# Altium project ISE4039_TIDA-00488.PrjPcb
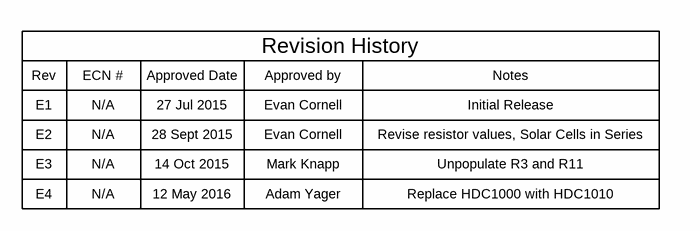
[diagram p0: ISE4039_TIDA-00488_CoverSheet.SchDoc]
TID: TIDA-00488; TechSupport: http://www.ti.com/support; SCH_Rev: E4; PRJ_Title: Energy Harvesting Ambient Light and Environment Sensor Node for Sub-1GHz Networks; PRJ_Number: ISE4039; PRJ_Engineer: Kelly Fernandez; PRJ_Customer: Public Release; PCB_Rev: E4; PCB_Layout: Evan Cornell; EVM_Orderable: N/A; CopyrightYear: 2016
4 sheets, 132 parts. Net scope: global (net labels, ports and power ports of the same name join across sheets).
Board file: ISE4039_TIDA-00488_TID.PcbDoc
Sheets:
  ISE4039_TIDA-00488_CoverSheet.SchDoc
  ISE4039_TIDA-00488_Energy Harvesting.SchDoc
  ISE4039_TIDA-00488_Wireless MCU & Sensors.SchDoc
  ISE4039_TIDA-00488_TID_Hardware.SchDoc

## Sheet ISE4039_TIDA-00488_CoverSheet.SchDoc: Cover Sheet
size 431 x 279 mm; Date: Not shown in title block; ApprovedBy: Not shown in title block; CheckedBy: Not shown in title block; Author: Not shown in title block; CompanyName: Not shown in title block; DrawnBy: Kelly Fernandez; Engineer: Not shown in title block; Organization: Not shown in title block; Address1: Not shown in title block; Address2: Not shown in title block; Address3: Not shown in title block; Address4: Not shown in title block; DocumentNumber: 1; Revision: Use project parameter SCH_Rev; SheetNumber: 1; SheetTotal: 4; PageSetup: Record=PageOptions¦CenterHorizontal=True¦CenterVertical=True¦PrintScale=1.00¦XCorrection=1.00¦YCorrection=1.00¦PrintKind=0¦BorderSize=5000000¦LeftOffset=0¦BottomOffset=0¦Orientation=2¦PaperLength=1000¦PaperWidth=1000¦Scale=100¦PaperSource=15¦PrintQuality=600¦MediaType=1¦DitherType=10¦PaperKind=Letter¦PrintScaleMode=1

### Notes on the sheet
- Rev
- E1
- ECN #
- N/A
- Approved Date
- 27 Jul 2015
- Approved by
- Evan Cornell
- Revision History
- Notes
- Initial Release
- E2
- E3
- 28 Sept 2015
- 14 Oct 2015
- Mark Knapp
- Revise resistor values, Solar Cells in Series
- Unpopulate R3 and R11
- E4
- 12 May 2016
- Adam Yager
- Replace HDC1000 with HDC1010

## Sheet ISE4039_TIDA-00488_Energy Harvesting.SchDoc: Energy Harvesting
size 431 x 279 mm; Date: Not shown in title block; ApprovedBy: Not shown in title block; CheckedBy: Not shown in title block; Author: Not shown in title block; CompanyName: Not shown in title block; DrawnBy: Kelly Fernandez; Engineer: Not shown in title block; Organization: Not shown in title block; Address1: Not shown in title block; Address2: Not shown in title block; Address3: Not shown in title block; Address4: Not shown in title block; DocumentNumber: 2; Revision: Use project parameter SCH_Rev; SheetNumber: 2; SheetTotal: 4; PageSetup: Record=PageOptions¦CenterHorizontal=True¦CenterVertical=True¦PrintScale=0.62¦XCorrection=1.00¦YCorrection=1.00¦PrintKind=0¦BorderSize=5000000¦LeftOffset=0¦BottomOffset=0¦Orientation=2¦PaperLength=1000¦PaperWidth=1000¦Scale=100¦PaperSource=15¦PrintQuality=600¦MediaType=1¦DitherType=10¦PrintScaleMode=1¦PaperKind=Letter
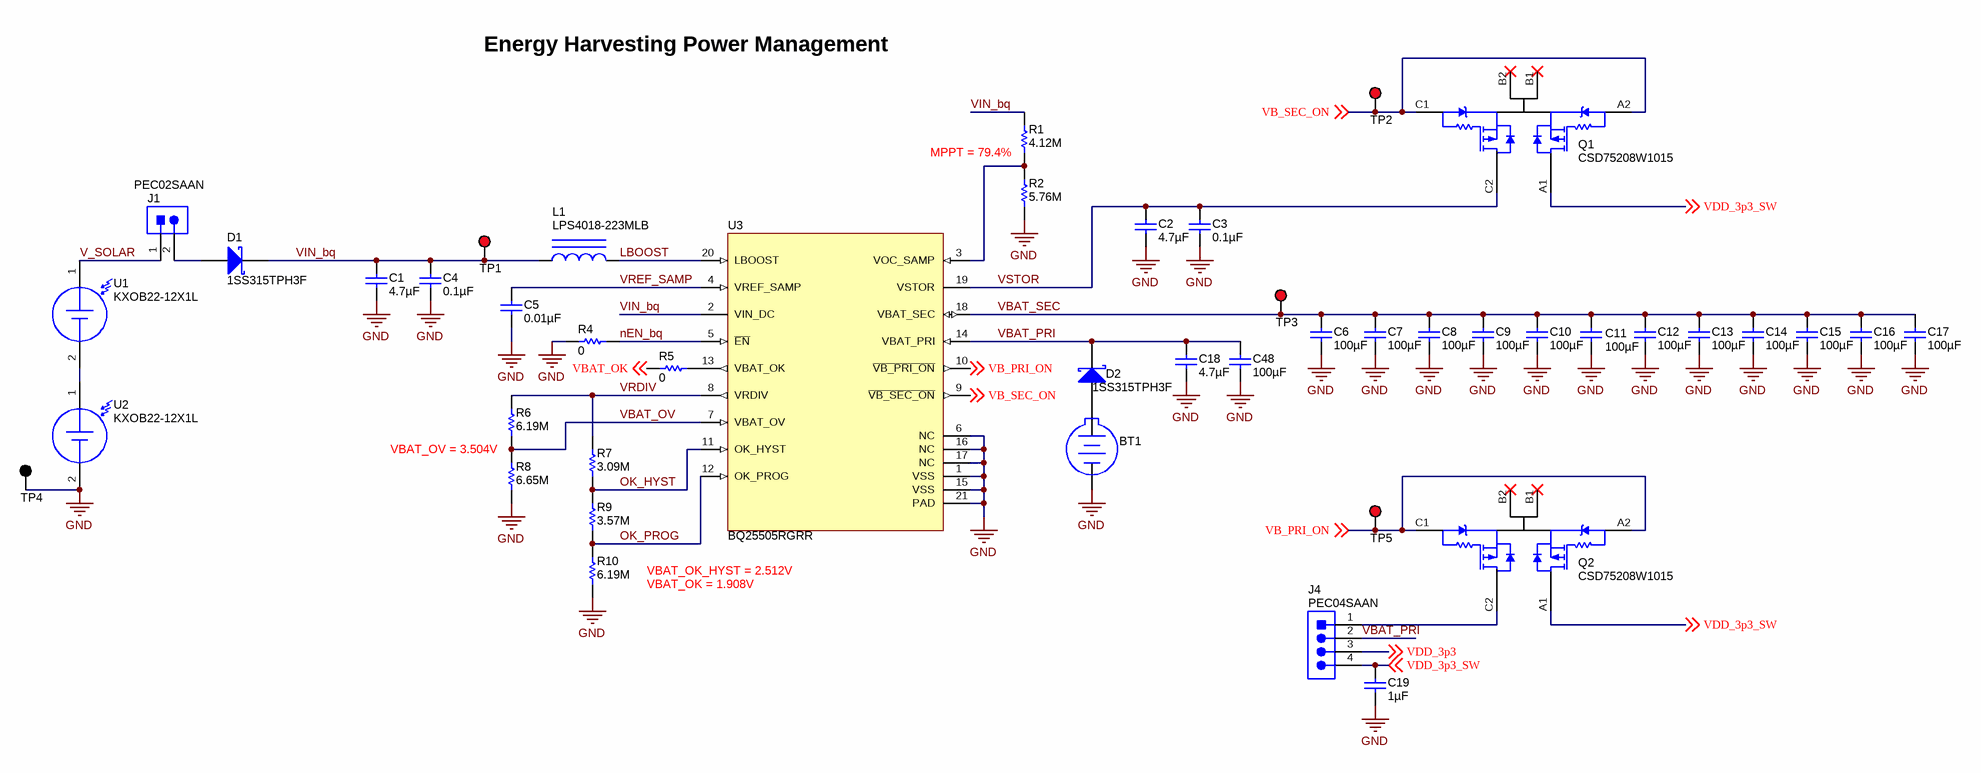
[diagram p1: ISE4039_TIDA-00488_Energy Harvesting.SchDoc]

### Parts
BT1  BS-7  [BAT_BS-7]  (value not drawn)
C1  ValueDisplayed: 4.7µF  [0402]  (hidden comment: C1005X5R1A475K050BC)
C2  ValueDisplayed: 4.7µF  [0402]  (hidden comment: C1005X5R1A475K050BC)
C3  ValueDisplayed: 0.1µF  [0402]  (hidden comment: GRM155R70J104KA01D)
C4  ValueDisplayed: 0.1µF  [0402]  (hidden comment: GRM155R70J104KA01D)
C5  ValueDisplayed: 0.01µF  [0402]  (hidden comment: C0402C103J5RACTU)
C6  ValueDisplayed: 100µF  [1206_190]  (hidden comment: C3216X5R1A107M160AC)
C7  ValueDisplayed: 100µF  [1206_190]  (hidden comment: C3216X5R1A107M160AC)
C8  ValueDisplayed: 100µF  [1206_190]  (hidden comment: C3216X5R1A107M160AC)
C9  ValueDisplayed: 100µF  [1206_190]  (hidden comment: C3216X5R1A107M160AC)
C10  ValueDisplayed: 100µF  [1206_190]  (hidden comment: C3216X5R1A107M160AC)
C11  ValueDisplayed: 100µF  [1206_190]  (hidden comment: C3216X5R1A107M160AC)
C12  ValueDisplayed: 100µF  [1206_190]  (hidden comment: C3216X5R1A107M160AC)
C13  ValueDisplayed: 100µF  [1206_190]  (hidden comment: C3216X5R1A107M160AC)
C14  ValueDisplayed: 100µF  [1206_190]  (hidden comment: C3216X5R1A107M160AC)
C15  ValueDisplayed: 100µF  [1206_190]  (hidden comment: C3216X5R1A107M160AC)
C16  ValueDisplayed: 100µF  [1206_190]  (hidden comment: C3216X5R1A107M160AC)
C17  ValueDisplayed: 100µF  [1206_190]  (hidden comment: C3216X5R1A107M160AC)
C18  ValueDisplayed: 4.7µF  [0402]  (hidden comment: C1005X5R1A475K050BC)
C19  ValueDisplayed: 1µF  [0402]  (hidden comment: GRM155R61A105KE15D)
C48  ValueDisplayed: 100µF  [1206_190]  (hidden comment: C3216X5R1A107M160AC)
D1  1SS315TPH3F  [sod-323]
D2  1SS315TPH3F  [sod-323]
J1  PEC02SAAN  [CONN_PEC02SAAN]
J4  PEC04SAAN  [SULLINS_PEC04SAAN]
L1  LPS4018-223MLB  [LPS4018]
Q1  CSD75208W1015  [YZC0006ABBB]
Q2  CSD75208W1015  [YZC0006ABBB]
R1  ValueDisplayed: 4.12M  [0402]  (hidden comment: CRCW04024M12FKED)
R2  ValueDisplayed: 5.76M  [0402]  (hidden comment: CRCW04025M76FKED)
R4  ValueDisplayed: 0  [0402]  (hidden comment: CRCW04020000Z0ED)
R5  ValueDisplayed: 0  [0402]  (hidden comment: CRCW04020000Z0ED)
R6  ValueDisplayed: 6.19M  [0402]  (hidden comment: CRCW04026M19FKED)
R7  ValueDisplayed: 3.09M  [0402]  (hidden comment: CRCW04023M09FKED)
R8  ValueDisplayed: 6.65M  [0402]  (hidden comment: CRCW04026M65FKED)
R9  ValueDisplayed: 3.57M  [0402]  (hidden comment: CRCW04023M57FKED)
R10  ValueDisplayed: 6.19M  [0402]  (hidden comment: CRCW04026M19FKED)
TP1  5000  [Keystone5000]  (value not drawn)
TP2  5000  [Keystone5000]  (value not drawn)
TP3  5000  [Keystone5000]  (value not drawn)
TP4  5001  [Keystone5001]  (value not drawn)
TP5  5000  [Keystone5000]  (value not drawn)
U1  KXOB22-12X1L  [IXYS_KXOB22-12X1L]
U2  KXOB22-12X1L  [IXYS_KXOB22-12X1L]
U3  BQ25505RGRR  [RGR0020A]

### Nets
GND: BT1.2(-) C1.2 C2.2 C3.2 C4.2 C5.2 C6.2 C7.2 C8.2 C9.2 C10.2 C11.2 C12.2 C13.2 C14.2 C15.2 C16.2 C17.2 C18.2 C19.2 C48.2 R2.1 R4.2 R8.1 R10.1 TP4.1 U2.2(-) U3.1(VSS) U3.6(NC) U3.15(VSS) U3.16(NC) U3.17(NC) U3.21(PAD)
LBOOST: L1.2 U3.20(LBOOST)
nEN_bq: R4.1 U3.5(~{EN})
OK_HYST: R7.1 R9.2 U3.11(OK_HYST)
OK_PROG: R9.1 R10.2 U3.12(OK_PROG)
V_SOLAR: J1.1 U1.1(+)
VB_PRI_ON: Q2.A2(G2) Q2.C1(G1) TP5.1 U3.10(~{VB_PRI_ON}) ; off-sheet VB_PRI_ON
VB_SEC_ON: Q1.A2(G2) Q1.C1(G1) TP2.1 U3.9(~{VB_SEC_ON}) ; off-sheet VB_SEC_ON
VBAT_OK: R5.1 ; off-sheet VBAT_OK
VBAT_OV: R6.1 R8.2 U3.7(VBAT_OV)
VBAT_PRI: C18.1 C48.1 D2.1(K) J4.2 U3.14(VBAT_PRI)
VBAT_SEC: C6.1 C7.1 C8.1 C9.1 C10.1 C11.1 C12.1 C13.1 C14.1 C15.1 C16.1 C17.1 TP3.1 U3.18(VBAT_SEC)
VDD_3p3: J4.3 ; off-sheet VDD_3p3
VDD_3p3_SW: C19.1 J4.4 Q1.A1(D2) Q2.A1(D2) ; off-sheet VDD_3p3_SW
VIN_bq: C1.1 C4.1 D1.1(K) L1.1 R1.2 TP1.1 U3.2(VIN_DC)
VRDIV: R6.2 R7.2 U3.8(VRDIV)
VREF_SAMP: C5.1 U3.4(VREF_SAMP)
VSTOR: C2.1 C3.1 Q1.C2(D1) U3.19(VSTOR)
NetBT1_1: BT1.1(+) D2.2(A)
NetD1_2: D1.2(A) J1.2
NetJ4_1: J4.1 Q2.C2(D1)
NetR1_1: R1.1 R2.2 U3.3(VOC_SAMP)
NetR5_2: R5.2 U3.13(VBAT_OK)
NetU1_2: U1.2(-) U2.1(+)

Not connected (* = marked no-connect by the designer): Q1 B1(S)* B2(S)*; Q2 B1(S)* B2(S)*

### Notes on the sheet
- Energy Harvesting Power Management
- MPPT = 79.4%
- VBAT_OV = 3.504V
- VBAT_OK_HYST = 2.512V
- VBAT_OK = 1.908V

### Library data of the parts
BT1 = BS-7: Battery Holder, CR2032, Retainer clip, TH; Manufacturer: Memory Protection Devices; SymbolCreator: a0412235
C1 C2 C18 = C1005X5R1A475K050BC: CAP, CERM, 4.7 µF, 10 V, +/- 10%, X5R, 0402; Manufacturer: TDK; Polarized: N; CompType: Capacitor; Value: 4.7uF; U/M: EA; Cap_F: 0.0000047; Tolerance_%: 10; Value1: Unknown; Value2: 10V; TaMin_C: -55; TaMax_C: 85; AEC Category: Q200
C3 C4 = GRM155R70J104KA01D: CAP, CERM, 0.1 µF, 6.3 V, +/- 10%, X7R, 0402; Manufacturer: MuRata; Polarized: N; CompType: Capacitor; Value: 0.1uF; U/M: EA; Cap_F: 0.0000001; Tolerance_%: 10; Value1: Unknown; VDC_V: 6.3; Value2: 6.3V; TaMin_C: -55; TaMax_C: 125
C5 = C0402C103J5RACTU: CAP, CERM, 0.01 µF, 50 V, +/- 5%, X7R, 0402; Manufacturer: Kemet; Polarized: N; CompType: Capacitor; Value: 0.01uF; U/M: EA; Cap_F: 0.00000001; Tolerance_%: 5; Value1: Unknown; VDC_V: 50; Value2: 50V; TaMin_C: -55; TaMax_C: 125; AEC Category: Q200
C6-C17 C48 = C3216X5R1A107M160AC: CAP, CERM, 100 µF, 10 V, +/- 20%, X5R, 1206_190; Manufacturer: TDK; Polarized: N; CompType: Capacitor; Value: 100uF; U/M: EA; Cap_F: 0.0001; Tolerance_%: 20; Value1: Unknown; VDC_V: 10; Value2: 10V; TaMin_C: -55; TaMax_C: 85; Cap_Case: 1206
C19 = GRM155R61A105KE15D: CAP, CERM, 1 µF, 10 V, +/- 10%, X5R, 0402; Manufacturer: MuRata; Polarized: N; CompType: Capacitor; Value: 1uF; U/M: EA; Cap_F: 0.000001; Tolerance_%: 10; Value1: Unknown; Value2: 10V; TaMin_C: -55; TaMax_C: 85
D1 D2 = 1SS315TPH3F: Diode, Schottky, 5V, 0.03A, SOD-323; Manufacturer: Toshiba; U/M: EA; Vf_V: 0.38; Value2: 0.38V; Io_A: 0.03; Vr_V: 5; TJmax_C: 125
J1 = PEC02SAAN: Header, 100mil, 2x1, Tin, TH; Manufacturer: Sullins Connector Solutions; SymbolCreator: a0412235; U/M: EA
J4 = PEC04SAAN: Header, 100mil, 4x1, Tin, TH; Manufacturer: Sullins Connector Solutions; SymbolCreator: a0412235; U/M: EA
L1 = LPS4018-223MLB: Inductor, Shielded Drum Core, Ferrite, 22 µH, 0.83 A, 0.36 ohm, SMD; Manufacturer: Coilcraft; Value: 22uH; Ind_H: 22.0E-6; ValueDisplayed: 22µH; Imax_A: 0.83; Irms: 0.9A @ 40C rise; Isat: 0.83A @ 30% inductance drop; DCR_ohm: 0.36; Value2: 0.83A
Q1 Q2 = CSD75208W1015: MOSFET, P-CH, -20 V, -1.6 A,; Manufacturer: Texas Instruments; Alternate Manufacturer: None; SymbolCreator: Altium; U/M: EA; ChType: P; Value: -20V; Value1: 0.09 ohm; Rdson45_ohm: 0.09; Value2: 1.9 nC; QgTyp_nC: 1.9; Vgs_V: -6
R1 = CRCW04024M12FKED: RES, 4.12 M, 1%, 0.063 W, 0402; Manufacturer: Vishay-Dale; CompType: Resistor; Value: 4.12Meg; Res_ohm: 4120000; Value_Code: 4M12; Tolerance_%: 1; Power_W: 0.063; Value2: 0.063W; VDC_V: 50; TempCo: 100 ppm/C; EIA_Code: E96; U/M: EA
R2 = CRCW04025M76FKED: RES, 5.76 M, 1%, 0.063 W, 0402; Manufacturer: Vishay-Dale; CompType: Resistor; Value: 5.76Meg; Res_ohm: 5760000; Value_Code: 5M76; Tolerance_%: 1; Power_W: 0.063; Value2: 0.063W; VDC_V: 50; TempCo: 100 ppm/C; EIA_Code: E96; U/M: EA; AEC Category: Q200
R4 R5 = CRCW04020000Z0ED: RES, 0, 5%, 0.063 W, 0402; Manufacturer: Vishay-Dale; CompType: Resistor; Value: 0; Value_Code: 0000; Tolerance_%: 5; Power_W: 0.063; Value2: 0.063W; VDC_V: 50; TempCo: 200 ppm/C; EIA_Code: E24; U/M: EA
R6 R10 = CRCW04026M19FKED: RES, 6.19 M, 1%, 0.063 W, 0402; Manufacturer: Vishay-Dale; CompType: Resistor; Value: 6.19Meg; Res_ohm: 6190000; Value_Code: 6M19; Tolerance_%: 1; Power_W: 0.063; Value2: 0.063W; VDC_V: 50; TempCo: 100 ppm/C; EIA_Code: E96; U/M: EA; AEC Category: Q200
R7 = CRCW04023M09FKED: RES, 3.09 M, 1%, 0.063 W, 0402; Manufacturer: Vishay-Dale; CompType: Resistor; Value: 3.09Meg; Res_ohm: 3090000; Value_Code: 3M09; Tolerance_%: 1; Power_W: 0.063; Value2: 0.063W; VDC_V: 50; TempCo: 100 ppm/C; EIA_Code: E96; U/M: EA; AEC Category: Q200
R8 = CRCW04026M65FKED: RES, 6.65 M, 1%, 0.063 W, 0402; Manufacturer: Vishay-Dale; CompType: Resistor; Value: 6.65Meg; Res_ohm: 6650000; Value_Code: 6M65; Tolerance_%: 1; Power_W: 0.063; Value2: 0.063W; VDC_V: 50; TempCo: 100 ppm/C; EIA_Code: E96; U/M: EA; AEC Category: Q200
R9 = CRCW04023M57FKED: RES, 3.57 M, 1%, 0.063 W, 0402; Manufacturer: Vishay-Dale; CompType: Resistor; Value: 3.57Meg; Res_ohm: 3570000; Value_Code: 3M57; Tolerance_%: 1; Power_W: 0.063; Value2: 0.063W; VDC_V: 50; TempCo: 100 ppm/C; EIA_Code: E96; U/M: EA; AEC Category: Q200
TP1-TP3 TP5 = 5000: Test Point, Miniature, Red, TH; Manufacturer: Keystone; CompType: Test Point Loop; U/M: EA
TP4 = 5001: Test Point, Miniature, Black, TH; Manufacturer: Keystone; CompType: Test Point Loop; U/M: EA
U1 U2 = KXOB22-12X1L: Monocrystalline Solar Cell, 22 X 7mm, SMD; Manufacturer: IXYS; SymbolCreator: a0412235; Value: 0.5V
U3 = BQ25505RGRR: Ultra Low Power Boost Converter with Battery Management for Energy Harvester Applications, RGR0020A; Alternate PartNumber: BQ25505RGRT; Manufacturer: Texas Instruments; SymbolCreator: a0412235; CompType: IC; U/M: EA

## Sheet ISE4039_TIDA-00488_Wireless MCU & Sensors.SchDoc: Bluetooth and Light Sensing
size 431 x 279 mm; Date: Not shown in title block; ApprovedBy: Not shown in title block; CheckedBy: Not shown in title block; Author: Not shown in title block; CompanyName: Not shown in title block; DrawnBy: Kelly Fernandez; Engineer: Not shown in title block; Organization: Not shown in title block; Address1: Not shown in title block; Address2: Not shown in title block; Address3: Not shown in title block; Address4: Not shown in title block; DocumentNumber: 3; Revision: Use project parameter SCH_Rev; SheetNumber: 3; SheetTotal: 4; PageSetup: Record=PageOptions¦CenterHorizontal=True¦CenterVertical=True¦PrintScale=1.00¦XCorrection=1.00¦YCorrection=1.00¦PrintKind=0¦BorderSize=5000000¦LeftOffset=0¦BottomOffset=0¦Orientation=2¦PaperLength=1000¦PaperWidth=1000¦Scale=100¦PaperSource=15¦PrintQuality=600¦MediaType=1¦DitherType=10¦PaperKind=Letter¦PrintScaleMode=1
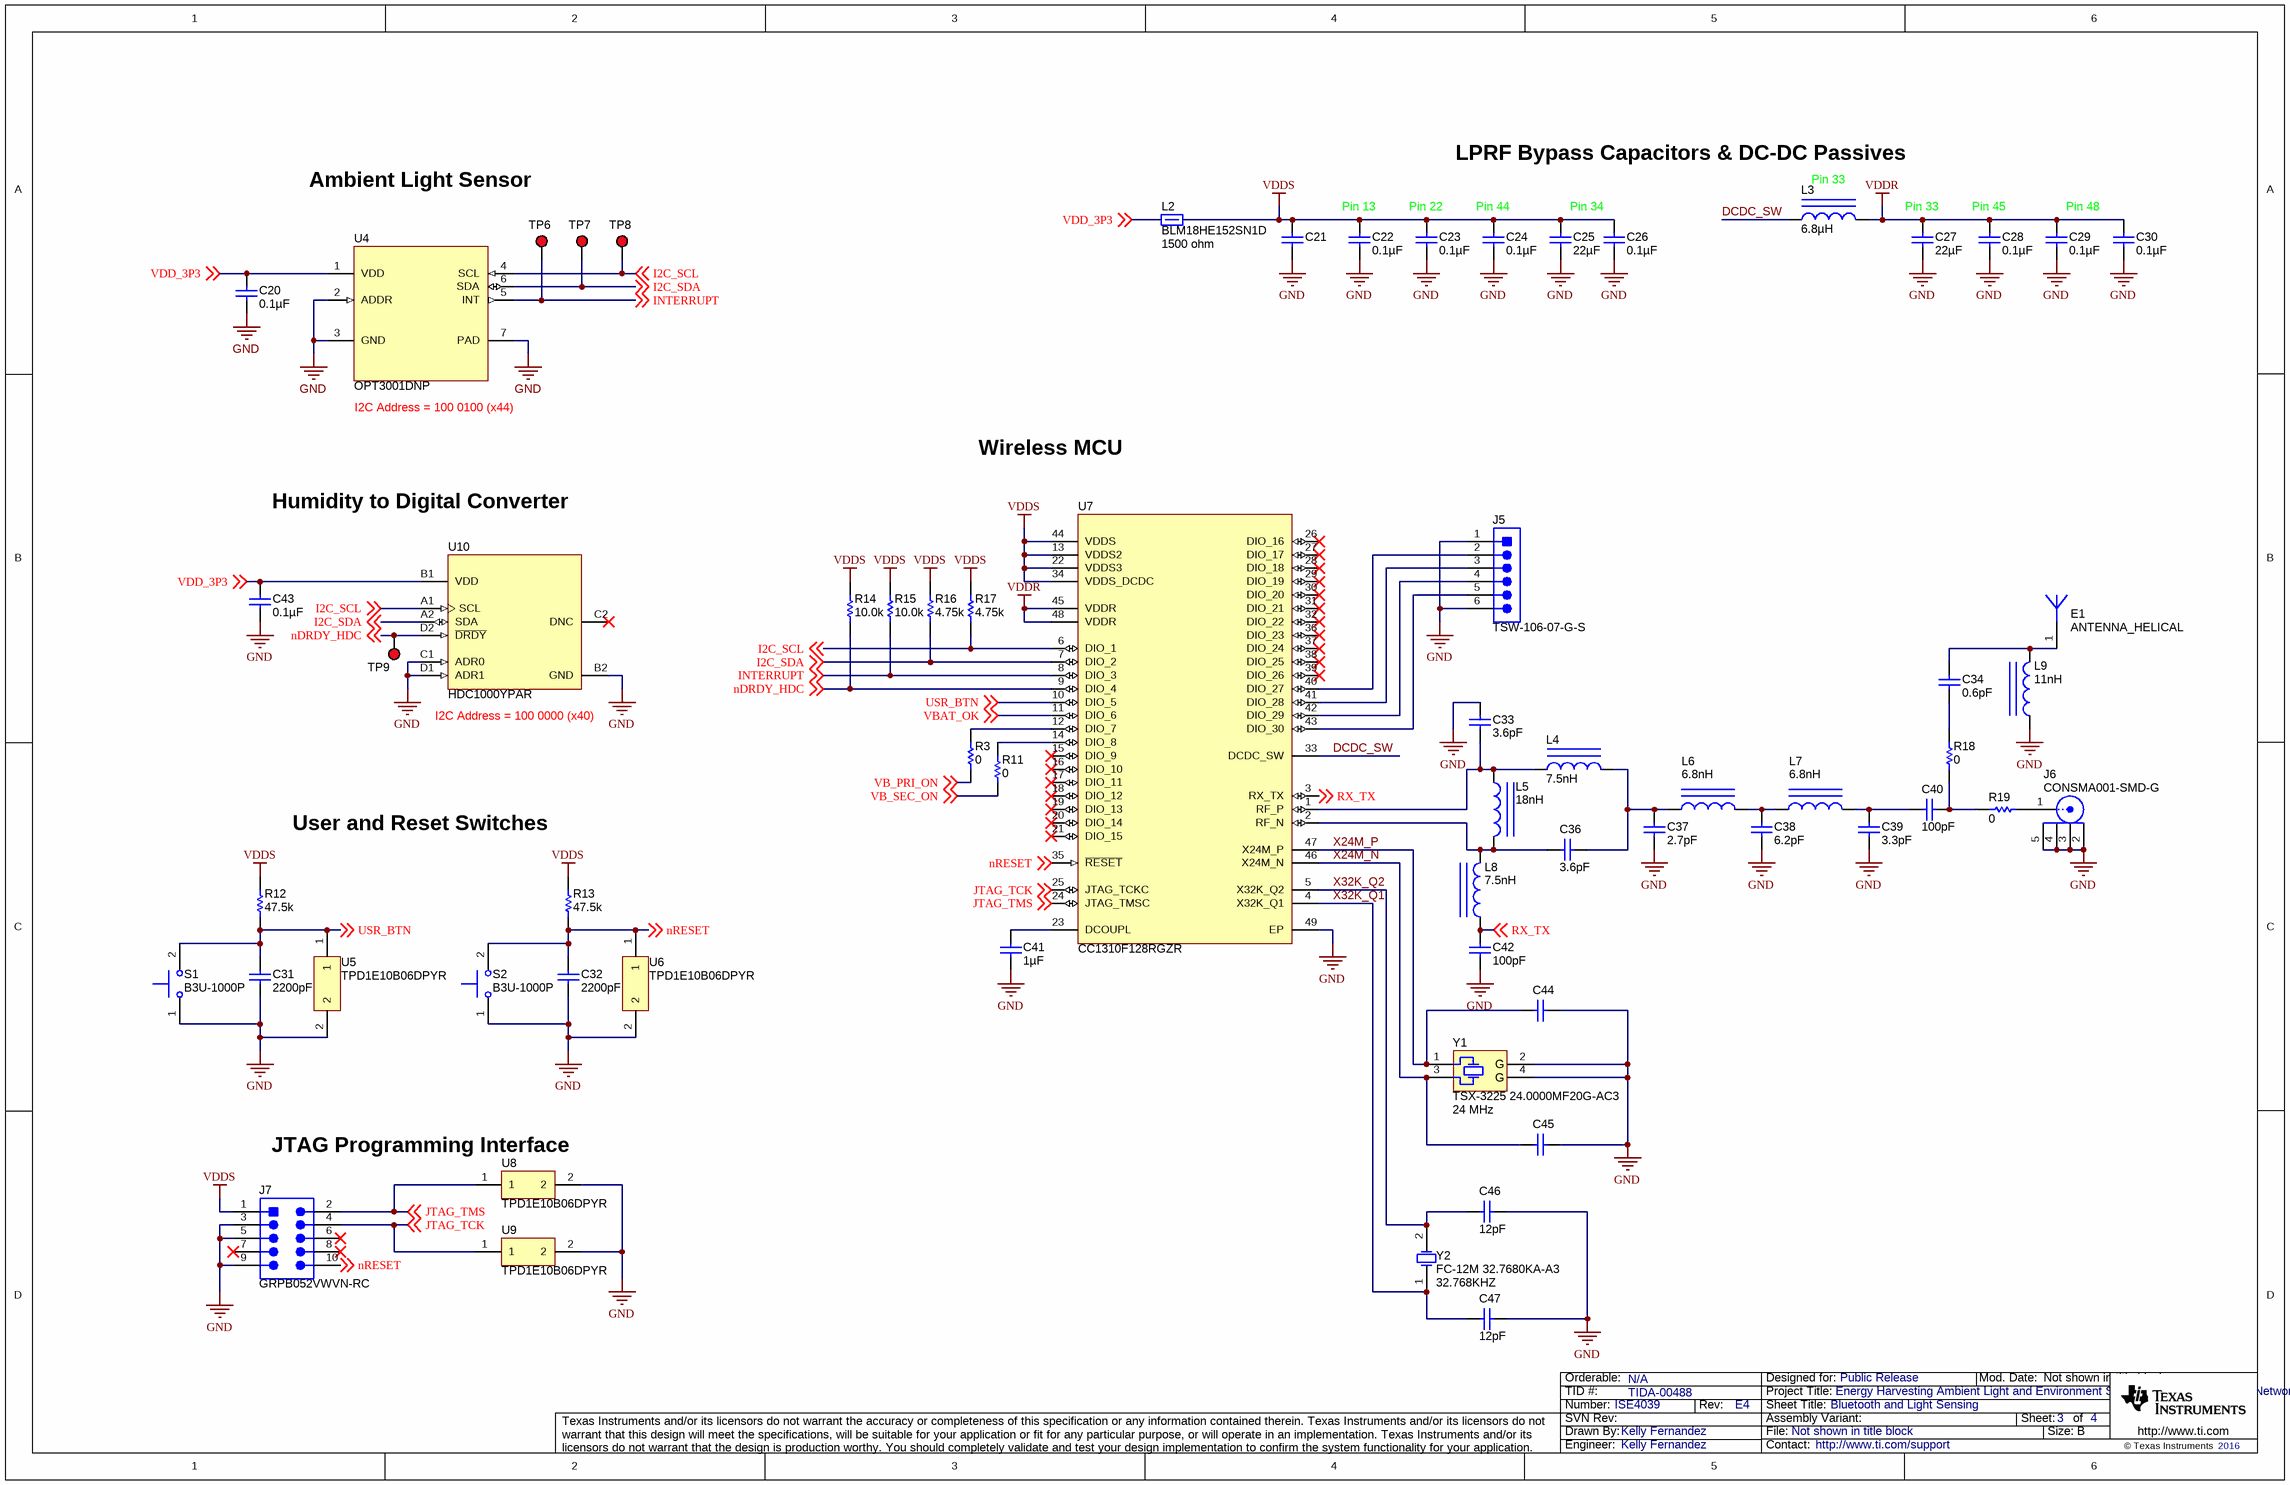
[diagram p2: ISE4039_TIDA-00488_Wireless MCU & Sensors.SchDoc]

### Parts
C20  ValueDisplayed: 0.1µF  [0402]  (hidden comment: GRM155R71C104KA88D)
C21  Used in BOM report  [0603]  (value not drawn)
C22  ValueDisplayed: 0.1µF  [0402]  (hidden comment: GRM155R71C104KA88D)
C23  ValueDisplayed: 0.1µF  [0402]  (hidden comment: GRM155R71C104KA88D)
C24  ValueDisplayed: 0.1µF  [0402]  (hidden comment: GRM155R71C104KA88D)
C25  ValueDisplayed: 22µF  [0603]  (hidden comment: C1608X5R0J226M080AC)
C26  ValueDisplayed: 0.1µF  [0402]  (hidden comment: GRM155R71C104KA88D)
C27  ValueDisplayed: 22µF  [0603]  (hidden comment: C1608X5R0J226M080AC)
C28  ValueDisplayed: 0.1µF  [0402]  (hidden comment: GRM155R71C104KA88D)
C29  ValueDisplayed: 0.1µF  [0402]  (hidden comment: GRM155R71C104KA88D)
C30  ValueDisplayed: 0.1µF  [0402]  (hidden comment: GRM155R71C104KA88D)
C31  ValueDisplayed: 2200pF  [0402]  (hidden comment: C1005X7R1H222K)
C32  ValueDisplayed: 2200pF  [0402]  (hidden comment: C1005X7R1H222K)
C33  ValueDisplayed: 3.6pF  [0402L]  (hidden comment: GRM1555C1H3R6CA01D)
C34  value 0.6pF  [0402L]  (hidden comment: GJM1555C1HR60BB01D)
C36  ValueDisplayed: 3.6pF  [0402L]  (hidden comment: GRM1555C1H3R6CA01D)
C37  ValueDisplayed: 2.7pF  [0402L]  (hidden comment: GRM1555C1H2R7CA01D)
C38  ValueDisplayed: 6.2pF  [0402L]  (hidden comment: GRM1555C1H6R2CA01D)
C39  ValueDisplayed: 3.3pF  [0402L]  (hidden comment: GRM1555C1H3R3CA01D)
C40  ValueDisplayed: 100pF  [0402L]  (hidden comment: GRM1555C1H101JA01D)
C41  ValueDisplayed: 1µF  [0402]  (hidden comment: C1005X5R1C105K050BC)
C42  ValueDisplayed: 100pF  [0402L]  (hidden comment: GRM1555C1H101JA01D)
C43  ValueDisplayed: 0.1µF  [0402]  (hidden comment: GRM155R71C104KA88D)
C44  GRM1555C1E120JA01D  [0402]  (value not drawn)
C45  GRM1555C1E120JA01D  [0402]  (value not drawn)
C46  ValueDisplayed: 12pF  [0402]  (hidden comment: GRM1555C1E120JA01D)
C47  ValueDisplayed: 12pF  [0402]  (hidden comment: GRM1555C1E120JA01D)
E1  ANTENNA_HELICAL  [ANTENNA_HELICAL]  (net tie)
J5  TSW-106-07-G-S  [TSW-106-07-G-S]
J6  CONSMA001-SMD-G  [Linx_CONSMA001-SMD-G]
J7  GRPB052VWVN-RC  [CONN_GRPB052VWVN-RC]
L2  BLM18HE152SN1D  value 1500 ohm  [0402S]
L3  ValueDisplayed: 6.8µH  [0805_145]  (hidden comment: MLZ2012N6R8LT000)
L4  ValueDisplayed: 7.5nH  [LQW15A_00_10]  (hidden comment: LQW15AN7N5G00D)
L5  value 18nH  [LQW15A_00_10]  (hidden comment: LQW15AN18NJ00D)
L6  value 6.8nH  [LQW15A_00_10]  (hidden comment: LQW15AN6N8G00D)
L7  value 6.8nH  [LQW15A_00_10]  (hidden comment: LQW15AN6N8G00D)
L8  ValueDisplayed: 7.5nH  [LQW15A_00_10]  (hidden comment: LQW15AN7N5G00D)
L9  ValueDisplayed: 11nH  [LQW15A_00_10]  (hidden comment: LQW15AN11NG00D)
R3  ValueDisplayed: 0  [0402]  (hidden comment: CRCW04020000Z0ED)
R11  ValueDisplayed: 0  [0402]  (hidden comment: CRCW04020000Z0ED)
R12  ValueDisplayed: 47.5k  [0402]  (hidden comment: CRCW040247K5FKED)
R13  ValueDisplayed: 47.5k  [0402]  (hidden comment: CRCW040247K5FKED)
R14  ValueDisplayed: 10.0k  [0402]  (hidden comment: CRCW040210K0FKED)
R15  ValueDisplayed: 10.0k  [0402]  (hidden comment: CRCW040210K0FKED)
R16  ValueDisplayed: 4.75k  [0402]  (hidden comment: CRCW04024K75FKED)
R17  ValueDisplayed: 4.75k  [0402]  (hidden comment: CRCW04024K75FKED)
R18  ValueDisplayed: 0  [0402L]  (hidden comment: CRCW04020000Z0ED)
R19  ValueDisplayed: 0  [0402L]  (hidden comment: CRCW04020000Z0ED)
S1  B3U-1000P  [SW_B3U-1000P]
S2  B3U-1000P  [SW_B3U-1000P]
TP6  5000  [Keystone5000]  (value not drawn)
TP7  5000  [Keystone5000]  (value not drawn)
TP8  5000  [Keystone5000]  (value not drawn)
TP9  5000  [Keystone5000]  (value not drawn)
U4  OPT3001DNP  [DNP0006A]
U5  TPD1E10B06DPYR  [DPY0002A]
U6  TPD1E10B06DPYR  [DPY0002A]
U7  CC1310F128RGZR  [RGZ0048A]
U8  TPD1E10B06DPYR  [DPY0002A]
U9  TPD1E10B06DPYR  [DPY0002A]
U10  HDC1000YPAR  [YPA0008AGAE]
Y1  TSX-3225 24.0000MF20G-AC3  Frequency: 24 MHz  [EPSON_TSX-3225]
Y2  FC-12M 32.7680KA-A3  Frequency: 32.768KHZ  [Epson_FC-12M]

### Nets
GND: C20.1 C21.2 C22.2 C23.2 C24.2 C25.2 C26.2 C27.2 C28.2 C29.2 C30.2 C31.1 C32.1 C33.1 C37.2 C38.2 C39.2 C41.1 C42.2 C43.1 C44.2 C45.2 C46.1 C47.1 J5.1 J5.6 J6.2 J6.3 J6.4 J6.5 J7.3 J7.5 J7.9 L9.1 S1.1 S2.1 U4.2(ADDR) U4.3(GND) U4.7(PAD) U5.2 U6.2 U7.49(EP) U8.2 U9.2 U10.B2(GND) U10.C1(ADR0) U10.D1(ADR1) Y1.2(GND) Y1.4(GND)
VDDR: C27.1 C28.1 C29.1 C30.1 L3.2 U7.45(VDDR) U7.48(VDDR)
VDDS: C21.1 C22.1 C23.1 C24.1 C25.1 C26.1 J7.1 L2.1 R12.2 R13.2 R14.2 R15.2 R16.2 R17.2 U7.13(VDDS2) U7.22(VDDS3) U7.34(VDDS_DCDC) U7.44(VDDS)
DCDC_SW: L3.1 U7.33(DCDC_SW)
I2C_SCL: R17.1 TP8.1 U4.4(SCL) U7.6(DIO_1) U10.A1(SCL) ; off-sheet I2C_SCL
I2C_SDA: R16.1 TP7.1 U4.6(SDA) U7.7(DIO_2) U10.A2(SDA) ; off-sheet I2C_SDA
INTERRUPT: R15.1 TP6.1 U4.5(INT) U7.8(DIO_3) ; off-sheet INTERRUPT
JTAG_TCK: J7.4 U7.25(JTAG_TCKC) U9.1 ; off-sheet JTAG_TCK
JTAG_TMS: J7.2 U7.24(JTAG_TMSC) U8.1 ; off-sheet JTAG_TMS
nDRDY_HDC: R14.1 TP9.1 U7.9(DIO_4) U10.D2(~{DRDY}) ; off-sheet nDRDY_HDC
nRESET: C32.2 J7.10 R13.1 S2.2 U6.1 U7.35(~{RESET}) ; off-sheet nRESET
RX_TX: C42.1 L8.1 U7.3(RX_TX) ; off-sheet RX_TX
USR_BTN: C31.2 R12.1 S1.2 U5.1 U7.10(DIO_5) ; off-sheet USR_BTN
VB_PRI_ON: R3.1 ; off-sheet VB_PRI_ON
VB_SEC_ON: R11.1 ; off-sheet VB_SEC_ON
VBAT_OK: U7.11(DIO_6) ; off-sheet VBAT_OK
VDD_3p3: C20.2 C43.2 L2.2 U4.1(VDD) U10.B1(VDD) ; off-sheet VDD_3P3
X24M_N: C45.1 U7.46(X24M_N) Y1.3
X24M_P: C44.1 U7.47(X24M_P) Y1.1
X32K_Q1: C47.2 U7.4(X32K_Q1) Y2.1(OSC1)
X32K_Q2: C46.2 U7.5(X32K_Q2) Y2.2(OSC2)
NetC33_2: C33.2 L4.1 L5.1 U7.1(RF_P)
NetC34_1: C34.1 E1.1 L9.2
NetC34_2: C34.2 R18.2
NetC36_1: C36.1 C37.1 L4.2 L6.1
NetC36_2: C36.2 L5.2 L8.2 U7.2(RF_N)
NetC38_1: C38.1 L6.2 L7.1
NetC39_1: C39.1 C40.2 L7.2
NetC40_1: C40.1 R18.1 R19.1
NetC41_2: C41.2 U7.23(DCOUPL)
NetJ5_2: J5.2 U7.40(DIO_27)
NetJ5_3: J5.3 U7.41(DIO_28)
NetJ5_4: J5.4 U7.42(DIO_29)
NetJ5_5: J5.5 U7.43(DIO_30)
NetJ6_1: J6.1 R19.2
NetR3_2: R3.2 U7.12(DIO_7)
NetR11_2: R11.2 U7.14(DIO_8)

Not connected (* = marked no-connect by the designer): J7 6* 7* 8*; U7 15(DIO_9)* 16(DIO_10)* 17(DIO_11)* 18(DIO_12)* 19(DIO_13)* 20(DIO_14)* 21(DIO_15)* 26(DIO_16)* 27(DIO_17)* 28(DIO_18)* 29(DIO_19)* 30(DIO_20)* 31(DIO_21)* 32(DIO_22)* 36(DIO_23)* 37(DIO_24)* 38(DIO_25)* 39(DIO_26)*; U10 C2(DNC)*

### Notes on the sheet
- LPRF Bypass Capacitors & DC-DC Passives
- Ambient Light Sensor
- (near C22) Pin 13
- (near C23) Pin 22
- (near C24) Pin 44
- Pin 34
- (near L3) Pin 33
- (near C27) Pin 33
- (near C28) Pin 45
- Pin 48
- I2C Address = 100 0100 (x44)
- Humidity to Digital Converter
- Wireless MCU
- (near U10) I2C Address = 100 0000 (x40)
- User and Reset Switches
- (near U8) JTAG Programming Interface

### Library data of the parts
C20 C22-C24 C26 C28-C30 = GRM155R71C104KA88D: CAP, CERM, 0.1 µF, 16 V, +/- 10%, X7R, 0402; Manufacturer: MuRata; Polarized: N; CompType: Capacitor; Value: 0.1uF; U/M: EA; Cap_F: 0.0000001; Tolerance_%: 10; Value1: Unknown; VDC_V: 16; Value2: 16V; TaMin_C: -55; TaMax_C: 125; AEC Category: Q200
C21 = Capacitor: CAP, CERM, xxxF, xxV, [TempCo], xx%, [PackageReference]; Polarized: N; U/M: EA
C25 C27 = C1608X5R0J226M080AC: CAP, CERM, 22 µF, 6.3 V, +/- 20%, X5R, 0603; Manufacturer: TDK; Polarized: N; CompType: Capacitor; Value: 22uF; U/M: EA; Cap_F: 0.000022; Tolerance_%: 20; Value1: Unknown; VDC_V: 6.3; Value2: 6.3V; TaMin_C: -55; TaMax_C: 85; AEC Category: Q200
C31 C32 = C1005X7R1H222K: CAP, CERM, 2200 pF, 50 V, +/- 10%, X7R, 0402; Manufacturer: TDK; Polarized: N; CompType: Capacitor; Value: 2200pF; U/M: EA; Cap_F: 0.0000000022; Tolerance_%: 10; ESR_ohm: 0.1433; Value1: 0.1433 ohm; VDC_V: 50; TaMin_C: -55; TaMax_C: 125
C33 C36 = GRM1555C1H3R6CA01D: CAP, CERM, 3.6 pF, 50 V, +/- 5%, C0G/NP0, 0402; Manufacturer: MuRata; Polarized: N; CompType: Capacitor; Value: 3.6pF; U/M: EA; Cap_F: 0.0000000000036; Tolerance_%: 5; Value1: Unknown; VDC_V: 50; Value2: 50V; TaMin_C: -55; TaMax_C: 125; Cap_Case: 0402
C34 = Capacitor: CAP, CERM, 0.6pF, 50V, NP0/C0G, +-0.1pF, 0402; Manufacturer: Murata; Polarized: N; U/M: EA
C37 = GRM1555C1H2R7CA01D: CAP, CERM, 2.7 pF, 50 V, +/- 5%, C0G/NP0, 0402; Manufacturer: MuRata; Polarized: N; CompType: Capacitor; Value: 2.7pF; U/M: EA; Cap_F: 0.0000000000027; Tolerance_%: 5; Value1: Unknown; VDC_V: 50; Value2: 50V; TaMin_C: -55; TaMax_C: 125; Cap_Case: 0402; AEC Category: Q200
C38 = GRM1555C1H6R2CA01D: CAP, CERM, 6.2 pF, 50 V, +/- 5%, C0G/NP0, 0402; Manufacturer: MuRata; Polarized: N; CompType: Capacitor; Value: 6.2pF; U/M: EA; Cap_F: 0.0000000000062; Tolerance_%: 5; Value1: Unknown; VDC_V: 50; Value2: 50V; TaMin_C: -55; TaMax_C: 125; Cap_Case: 0402; AEC Category: Q200
C39 = GRM1555C1H3R3CA01D: CAP, CERM, 3.3 pF, 50 V, +/- 5%, C0G/NP0, 0402; Manufacturer: MuRata; Polarized: N; CompType: Capacitor; Value: 3.3pF; U/M: EA; Cap_F: 0.0000000000033; Tolerance_%: 5; Value1: Unknown; VDC_V: 50; Value2: 50V; TaMin_C: -55; TaMax_C: 125; Cap_Case: 0402; AEC Category: Q200
C40 = GRM1555C1H101JA01D: CAP, CERM, 100 pF, 50 V, +/- 5%, C0G/NP0, 0402; Manufacturer: MuRata; Polarized: N; CompType: Capacitor; Value: 100pF; U/M: EA; Cap_F: 0.0000000001; Tolerance_%: 5; Value1: Unknown; VDC_V: 50; Value2: 50V; TaMin_C: -55; TaMax_C: 125; Cap_Case: 0402; AEC Category: Q200
C41 = C1005X5R1C105K050BC: CAP, CERM, 1 µF, 16 V, +/- 10%, X5R, 0402; Manufacturer: TDK; Polarized: N; CompType: Capacitor; Value: 1uF; U/M: EA; Cap_F: 0.000001; Tolerance_%: 10; Value1: Unknown; VDC_V: 16; Value2: 16V; TaMin_C: -55; TaMax_C: 85; AEC Category: Q200
C42 = GRM1555C1H101JA01D: CAP, CERM, 100 pF, 50 V, +/- 5%, C0G/NP0, 0402; Manufacturer: MuRata; Polarized: N; CompType: Capacitor; Value: 100pF; U/M: EA; Cap_F: 0.0000000001; Tolerance_%: 5; Value1: Unknown; VDC_V: 50; Value2: 50V; TaMin_C: -55; TaMax_C: 125; Cap_Case: 0402
C43 = GRM155R71C104KA88D: CAP, CERM, 0.1 µF, 16 V, +/- 10%, X7R, 0402; Manufacturer: MuRata; Polarized: N; CompType: Capacitor; Value: 0.1uF; U/M: EA; Cap_F: 0.0000001; Tolerance_%: 10; Value1: Unknown; VDC_V: 16; Value2: 16V; TaMin_C: -55; TaMax_C: 125
C44-C47 = GRM1555C1E120JA01D: CAP, CERM, 12 pF, 25 V, +/- 5%, C0G/NP0, 0402; Manufacturer: MuRata; Polarized: N; CompType: Capacitor; Value: 12pF; U/M: EA; Cap_F: 0.000000000012; Tolerance_%: 5; Value1: Unknown; VDC_V: 25; Value2: 25V; TaMin_C: -55; TaMax_C: 125; AEC Category: Q200
E1 = ANTENNA_HELICAL: PCB Antenna. There is nothing to buy or mount.; SymbolCreator: Altium
J5 = TSW-106-07-G-S: Header, 100mil, 6x1, Gold, TH; Manufacturer: Samtec; SymbolCreator: a0412235; U/M: EA
J6 = CONSMA001-SMD-G: Jack, SMA, PCB, Gold, SMT; Manufacturer: Linx Technologies; SymbolCreator: X0208326; U/M: EA
J7 = GRPB052VWVN-RC: Header, 50mil, 5x2, Gold, TH; Manufacturer: Sullins Connector Solutions; SymbolCreator: a0412235; U/M: EA
L2 = BLM18HE152SN1D: Ferrite Bead, 1500 ohm @ 100 MHz, 0.5 A, 0603_950; Manufacturer: MuRata; Imax_A: 0.5; Value1: 0.5 ohm; Value2: 0.5A; ZTyp@100MHz_Ohm: 1500
L3 = MLZ2012N6R8LT000: Inductor, Multilayer, Ferrite, 6.8 µH, 0.11 A, 0.25 ohm, SMD; Manufacturer: TDK; Value: 6.8uH; Ind_H: 6.8E-6; Imax_A: 0.11; Irms: 0.55A @ 20C rise; Isat: 0.11A @ 50% inductance drop; DCR_ohm: 0.25; Value2: 0.11A; AEC Category: Q200
L4 L8 = LQW15AN7N5G00D: Inductor, Wirewound, 7.5 nH, 0.57 A, 0.13 ohm, SMD; Manufacturer: MuRata; Value: 7.5nH; Ind_H: 7.5E-9; Imax_A: 0.57; Irms: 0.57A @ C rise; DCR_ohm: 0.13; Value2: 0.57A
L5 = LQW15AN18NJ00D: Inductor, Wirewound, 18 nH, 0.37 A, 0.27 ohm, SMD; Manufacturer: MuRata; Ind_H: 18.0E-9; Imax_A: 0.37; DCR_ohm: 0.27; Value2: 0.37A
L6 L7 = LQW15AN6N8G00D: Inductor, Wirewound, 6.8 nH, 0.7 A, 0.09 ohm, SMD; Manufacturer: MuRata; Ind_H: 6.8E-9; Imax_A: 0.7; DCR_ohm: 0.09; Value2: 0.7A
L9 = LQW15AN11NG00D: Inductor, Wirewound, 11 nH, 0.5 A, 0.14 ohm, SMD; Manufacturer: MuRata; Value: 11nH; Value2: 0.5A; Ind_H: 11.0E-9; Imax_A: 0.5; Isat: 0.5A @ % inductance drop; DCR_ohm: 0.14; AEC Category: Q200; AEC Qualified: N
R3 R11 = CRCW04020000Z0ED: RES, 0, 5%, 0.063 W, 0402; Manufacturer: Vishay-Dale; CompType: Resistor; Value: 0; Value_Code: 0000; Tolerance_%: 5; Power_W: 0.063; Value2: 0.063W; VDC_V: 50; TempCo: 200 ppm/C; EIA_Code: E24; U/M: EA; AEC Category: Q200
R12 R13 = CRCW040247K5FKED: RES, 47.5 k, 1%, 0.063 W, 0402; Manufacturer: Vishay-Dale; CompType: Resistor; Res_ohm: 47500; Value: 47.5k; Value_Code: 47k5; Tolerance_%: 1; Power_W: 0.063; Value2: 0.063W; VDC_V: 50; TempCo: 100 ppm/C; EIA_Code: E96; U/M: EA
R14 R15 = CRCW040210K0FKED: RES, 10.0 k, 1%, 0.063 W, 0402; Manufacturer: Vishay-Dale; CompType: Resistor; Value: 10.0k; Res_ohm: 10000; Value_Code: 10k0; Tolerance_%: 1; Power_W: 0.063; Value2: 0.063W; VDC_V: 50; TempCo: 100 ppm/C; EIA_Code: E96; U/M: EA
R16 R17 = CRCW04024K75FKED: RES, 4.75 k, 1%, 0.063 W, 0402; Manufacturer: Vishay-Dale; CompType: Resistor; Value: 4.75k; Res_ohm: 4750; Value_Code: 4k75; Tolerance_%: 1; Power_W: 0.063; Value2: 0.063W; VDC_V: 50; TempCo: 100 ppm/C; EIA_Code: E96; U/M: EA
R18 R19 = CRCW04020000Z0ED: as R4 on sheet ISE4039_TIDA-00488_Energy Harvesting
S1 S2 = B3U-1000P: SWITCH TACTILE SPST-NO 0.05A 12V; Manufacturer: Omron Electronic Components; SymbolCreator: a0412235; VDC_V: 12; SwitchFunction: Off-Mom; PositionCount: 1; CurrentRating_mA: 50
TP6-TP9 = 5000: as TP1 on sheet ISE4039_TIDA-00488_Energy Harvesting
U4 = OPT3001DNP: Ambient Light Sensor, DNP0006A; Manufacturer: Texas Instruments; SymbolCreator: a0411947; CompType: IC; U/M: EA
U5 U6 U8 U9 = TPD1E10B06DPYR: ESD in 0402 Package with 10 pF Capacitance and 6 V Breakdown, 1 Channel, -40 to +125 degC, 2-pin X2SON (DPY), Green (RoHS & no Sb/Br); Manufacturer: Texas Instruments; Alternate Manufacturer: None; Alternate PartNumber: Equivalent; Breakdown Voltage(Min)(V): 6; Eco-Plan: TBD; IEC 61000-4-2 Air-Gap(+/- kV): 30; IO Capacitance(Typ)(pF): 10; SubFamily: ESD Solution
U7 = CC1310F128RGZR: Sub-1 GHz and 2.4 GHz Multi-standard RF IC Family, RGZ0048A; Alternate PartNumber: CC1310F128RGZT; Manufacturer: Texas Instruments; SymbolCreator: Altium; U/M: EA
U10 = HDC1000YPAR: HDC1000 Low power integrated humidity and temperature Sensor, YPA0008AGAE; Alternate Manufacturer: Texas Instruments; Alternate PartNumber: HDC1000YPAT; SymbolCreator: Altium; CompType: IC; U/M: EA
Y1 = TSX-3225 24.0000MF20G-AC3: Crystal, 24 MHz, 9 pF, SMD; Manufacturer: Epson; SymbolCreator: a0412235; U/M: EA; TaMin_C: -40; TaMax_C: 85; Frequency Stability: ±20ppm
Y2 = FC-12M 32.7680KA-A3: Crystal, 32.768kHz, 12.5pF, SMD; Manufacturer: Epson; SymbolCreator: a0412235; U/M: EA; TaMin_C: -40; TaMax_C: 85; Frequency Stability: ±20ppm

## Sheet ISE4039_TIDA-00488_TID_Hardware.SchDoc: Hardware
size 431 x 279 mm; Date: Not shown in title block; ApprovedBy: Not shown in title block; CheckedBy: Not shown in title block; Author: Not shown in title block; CompanyName: Not shown in title block; DrawnBy: Kelly Fernandez; Engineer: Not shown in title block; Organization: Not shown in title block; Address1: Not shown in title block; Address2: Not shown in title block; Address3: Not shown in title block; Address4: Not shown in title block; DocumentNumber: 4; Revision: Use project parameter SCH_Rev; SheetNumber: 4; SheetTotal: 4; PageSetup: Record=PageOptions¦CenterHorizontal=True¦CenterVertical=True¦PrintScale=1.00¦XCorrection=1.00¦YCorrection=1.00¦PrintKind=0¦BorderSize=5000000¦LeftOffset=0¦BottomOffset=0¦Orientation=2¦PaperLength=1000¦PaperWidth=1000¦Scale=100¦PaperSource=15¦PrintQuality=600¦MediaType=1¦DitherType=10¦PaperKind=Letter¦PrintScaleMode=1
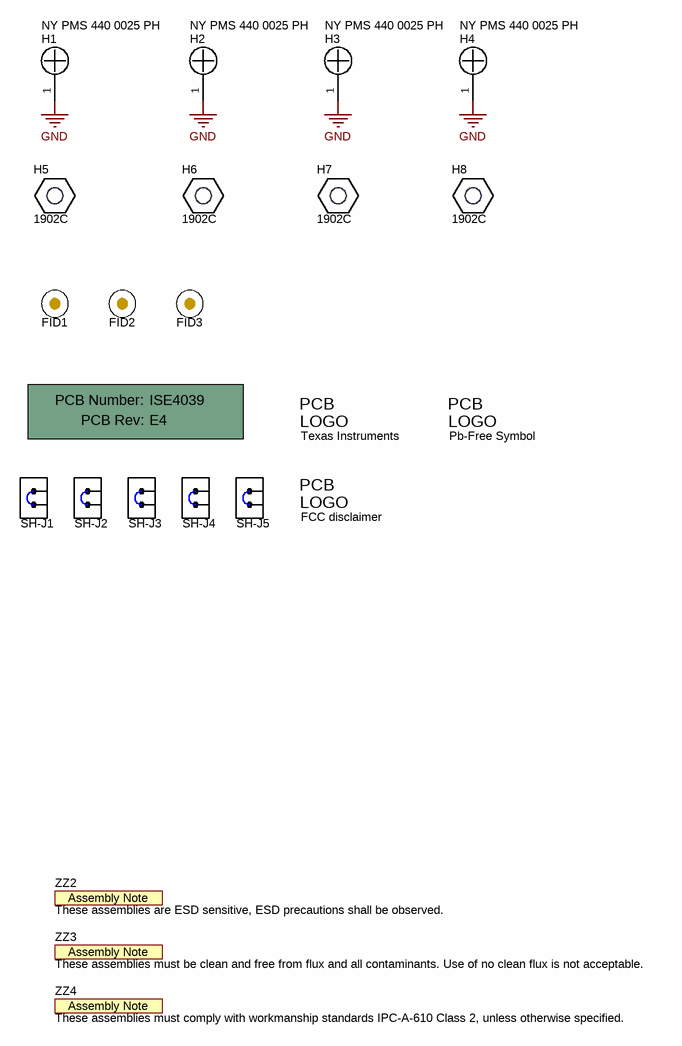
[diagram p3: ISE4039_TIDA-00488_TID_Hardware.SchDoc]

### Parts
!PCB  Printed Circuit Board  (value not drawn)  (mechanical)
FID1  Fiducial  [Fiducial10-20]  (value not drawn)
FID2  Fiducial  [Fiducial10-20]  (value not drawn)
FID3  Fiducial  [Fiducial10-20]  (value not drawn)
H1  NY PMS 440 0025 PH  [NY PMS 440 0025 PH]
H2  NY PMS 440 0025 PH  [NY PMS 440 0025 PH]
H3  NY PMS 440 0025 PH  [NY PMS 440 0025 PH]
H4  NY PMS 440 0025 PH  [NY PMS 440 0025 PH]
H5  1902C  [Keystone_1902C]
H6  1902C  [Keystone_1902C]
H7  1902C  [Keystone_1902C]
H8  1902C  [Keystone_1902C]
Logo1  Texas Instruments  [TI_Symbol_Overlay_Small]  (no BOM)
Logo2  Pb-Free Symbol  [Pb-Free_Overlay_Small]  (no BOM)
Logo3  FCC disclaimer  [FCC_disclaimer_stacked]  (no BOM)
SH-J1  2SN-BK-G  [2SN-BK-G]  (value not drawn)
SH-J2  2SN-BK-G  [2SN-BK-G]  (value not drawn)
SH-J3  2SN-BK-G  [2SN-BK-G]  (value not drawn)
SH-J4  2SN-BK-G  [2SN-BK-G]  (value not drawn)
SH-J5  2SN-BK-G  [2SN-BK-G]  (value not drawn)
ZZ2  These assemblies are ESD sensitive, ESD precautions shall be observed.  [AssemblyNote]  (no BOM)
ZZ3  These assemblies must be clean and free from flux and all contaminants. Use of no clean flux is not acceptable.  [AssemblyNote]  (no BOM)
ZZ4  These assemblies must comply with workmanship standards IPC-A-610 Class 2, unless otherwise specified.  [AssemblyNote]  (no BOM)

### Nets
GND: H1.1 H2.1 H3.1 H4.1

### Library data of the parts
!PCB = PCB: Manufacturer: Any; PartNumber: ISE4039; SymbolCreator: a0412235
FID1-FID3 = Fiducial: Fiducial mark.  There is nothing to buy or mount.; SymbolCreator: codlsc
H1-H4 = NY PMS 440 0025 PH: Machine Screw, Round, #4-40 x 1/4, Nylon, Philips panhead; Manufacturer: B&F Fastener Supply; CompType: Hardware; SymbolCreator: codlsc; U/M: EA
H5-H8 = 1902C: Standoff, Hex, 0.5"L #4-40 Nylon; Manufacturer: Keystone; CompType: Hardware
Logo1 = TI_Logo: Texas Instrument Corporate Signature; SymbolCreator: codlsc
Logo2 = Pb-Free: SymbolCreator: a0412235
Logo3 = FCC_disclaimer: SymbolCreator: codlsc
SH-J1-SH-J5 = 2SN-BK-G: Shunt, 2mm, Gold plated, Black; Manufacturer: Samtec; Value: 1x2; Note: You can "mate" this to a header by matching the designator.  i.e. use SH-J3 for header J3
ZZ2-ZZ4 = AssemblyNote: SymbolCreator: codlsc

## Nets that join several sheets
GND: ISE4039_TIDA-00488_Energy Harvesting (33 pins), ISE4039_TIDA-00488_Wireless MCU & Sensors (49 pins), ISE4039_TIDA-00488_TID_Hardware (H1.1 H2.1 H3.1 H4.1)
VB_PRI_ON: ISE4039_TIDA-00488_Energy Harvesting (Q2.A2 Q2.C1 TP5.1 U3.10), ISE4039_TIDA-00488_Wireless MCU & Sensors (R3.1)
VB_SEC_ON: ISE4039_TIDA-00488_Energy Harvesting (Q1.A2 Q1.C1 TP2.1 U3.9), ISE4039_TIDA-00488_Wireless MCU & Sensors (R11.1)
VBAT_OK: ISE4039_TIDA-00488_Energy Harvesting (R5.1), ISE4039_TIDA-00488_Wireless MCU & Sensors (U7.11)
VDD_3p3: ISE4039_TIDA-00488_Energy Harvesting (J4.3), ISE4039_TIDA-00488_Wireless MCU & Sensors (5 pins)

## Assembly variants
001: not fitted C21 C30 C44 C45 FID1 FID2 FID3 J5 J6 R3 R11 R19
